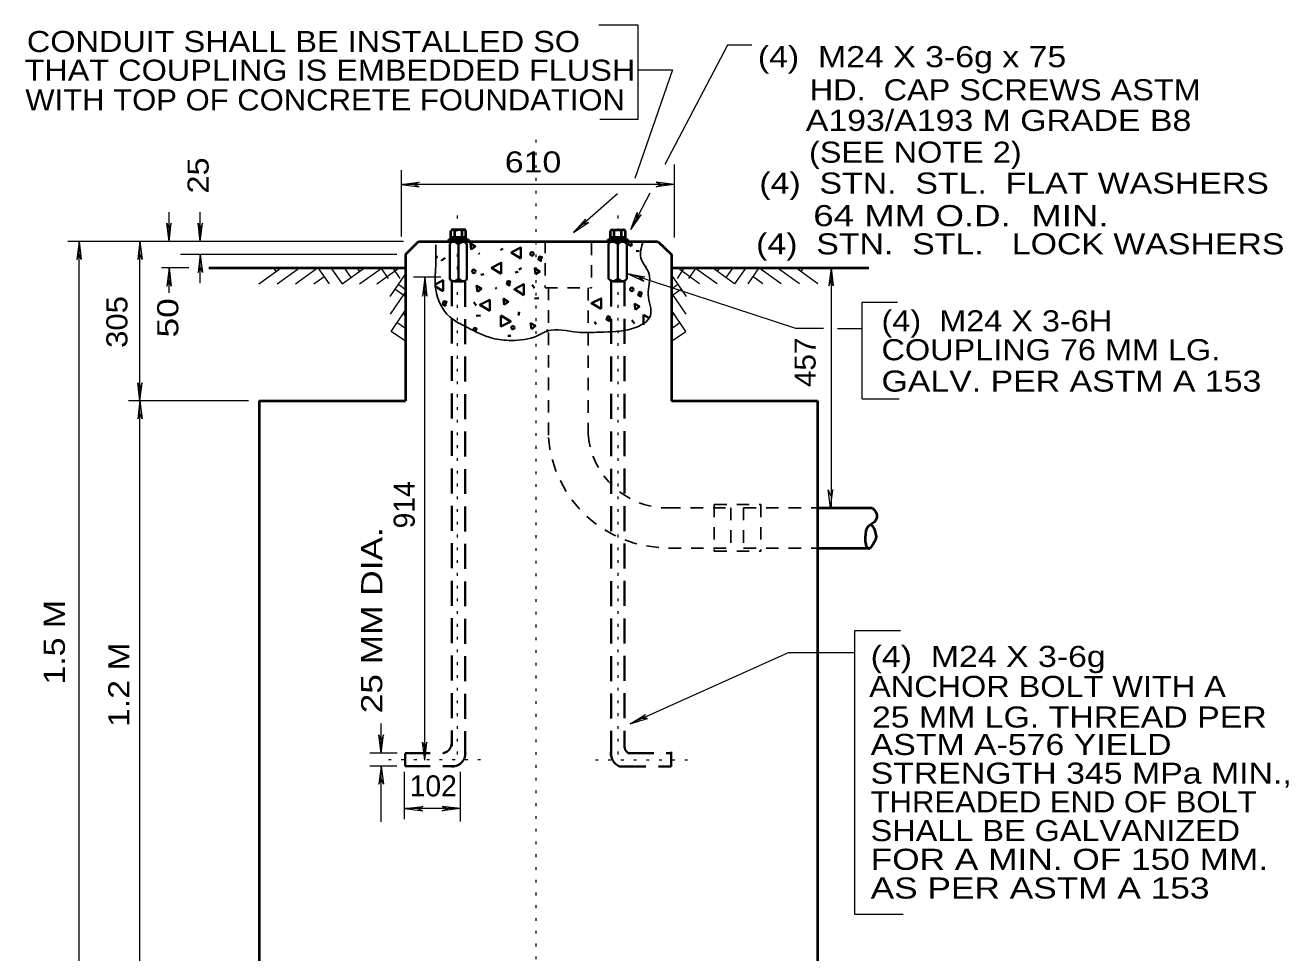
# Model space of a CAD drawing. Extents: x 312583 to 312854, y 144419 to 144597.
# Drawn here: x 312759.06 to 312804.6, y 144492.78 to 144526.21 of the extents above; entities that cross this region are included whole.
import ezdxf

# ---------------------------------------------------------------- set-up
doc = ezdxf.new("R2010")
doc.units = 0
doc.header["$LTSCALE"] = 0.3
for name, pattern in [('DOTTED', [1.5, 0.3, -1.2]), ('MEDIUM_DASHED', [4.5, 3, -1.5]), ('SHORT_DASHED', [2.7, 1.5, -1.2])]:
    doc.linetypes.add(name, pattern=pattern)
doc.layers.add('1', color=7, linetype='Continuous', lineweight=25)
doc.layers.add('2', color=7, linetype='Continuous', lineweight=13)

msp = doc.modelspace()

# ---------------------------------------------------------------- linework, layer by layer
at = {"layer": '1', "linetype": 'DOTTED', "lineweight": 13}
for p, q in [((312774.6248, 144519.352), (312774.6248, 144499.8557)), ((312780.4208, 144519.352), (312780.4208, 144499.8557)), ((312772.1485, 144499.7407), (312775.4988, 144499.7407)), ((312779.6081, 144499.733), (312782.9431, 144499.733))]:
    msp.add_line(p, q, dxfattribs=at)
at = {"layer": '1', "lineweight": 40}
for p, q in [((312774.4025, 144518.4857), (312774.4025, 144518.8)), ((312774.4025, 144518.5777), (312774.9391, 144518.5777)), ((312774.4715, 144518.846), (312774.8778, 144518.846)), ((312774.5405, 144518.5777), (312774.5405, 144518.8)), ((312774.8088, 144518.5777), (312774.8088, 144518.8)), ((312774.9391, 144518.4857), (312774.9391, 144518.8)), ((312780.1525, 144518.4857), (312780.1525, 144518.8)), ((312780.1525, 144518.57), (312780.6891, 144518.57)), ((312780.2138, 144518.8384), (312780.6201, 144518.8384)), ((312780.2828, 144518.57), (312780.2828, 144518.8)), ((312780.5511, 144518.57), (312780.5511, 144518.8)), ((312780.6891, 144518.4857), (312780.6891, 144518.8)), ((312772.7618, 144517.949), (312773.2371, 144518.4244)), ((312773.2371, 144518.4244), (312781.8621, 144518.4244)), ((312774.3105, 144518.4857), (312775.0311, 144518.4857)), ((312774.3105, 144518.4857), (312774.3105, 144518.4244)), ((312775.0311, 144518.4857), (312775.0311, 144518.4244)), ((312780.0605, 144518.4857), (312780.7811, 144518.4857)), ((312780.0605, 144518.4857), (312780.0605, 144518.4244)), ((312780.7735, 144518.4857), (312780.7735, 144518.4244)), ((312781.8621, 144518.4244), (312782.3451, 144517.949)), ((312772.7618, 144517.949), (312772.7618, 144512.6744)), ((312782.3451, 144517.949), (312782.3451, 144512.6744)), ((312765.6701, 144517.466), (312772.7618, 144517.466)), ((312782.3451, 144517.466), (312789.4598, 144517.466)), ((312774.5251, 144516.9907), (312774.8318, 144516.9907)), ((312780.2598, 144516.9907), (312780.5818, 144516.9907)), ((312767.4871, 144512.6744), (312767.4871, 144489.6744)), ((312767.4871, 144512.6744), (312772.7618, 144512.6744)), ((312782.3451, 144512.6744), (312787.6121, 144512.6744)), ((312787.6121, 144512.6744), (312787.6121, 144489.6744)), ((312787.6351, 144508.818), (312789.5825, 144508.818)), ((312787.6351, 144507.369), (312789.4828, 144507.369))]:
    msp.add_line(p, q, dxfattribs=at)
at = {"layer": '1', "lineweight": 35}
for p, q in [((312774.3565, 144518.34), (312774.3565, 144517.0444)), ((312774.6708, 144518.3247), (312774.6708, 144517.0597)), ((312774.9775, 144518.34), (312774.9775, 144517.0444)), ((312776.1811, 144518.11), (312776.2731, 144518.1637)), ((312780.0835, 144518.34), (312780.0835, 144517.0674)), ((312780.4208, 144518.3477), (312780.4208, 144517.052)), ((312780.6048, 144518.432), (312780.9115, 144518.248)), ((312780.7351, 144518.34), (312780.7351, 144517.0597)), ((312780.9115, 144518.248), (312780.9115, 144518.4397)), ((312781.0725, 144518.0717), (312781.1875, 144518.087)), ((312774.1878, 144517.8264), (312774.0498, 144517.7267)), ((312775.4068, 144517.995), (312775.4298, 144517.9567)), ((312775.4835, 144517.2207), (312775.5908, 144517.2437)), ((312776.7178, 144517.305), (312776.8251, 144517.328)), ((312776.8481, 144517.4047), (312776.9401, 144517.4584)), ((312773.8428, 144516.799), (312774.1188, 144516.6304)), ((312776.0048, 144516.7607), (312776.0431, 144516.707)), ((312777.3235, 144516.8604), (312777.4155, 144516.7377)), ((312777.4078, 144516.3697), (312777.5688, 144516.3774)), ((312775.2228, 144516.2317), (312775.3148, 144516.109)), ((312776.8405, 144515.7487), (312776.8558, 144515.8867)), ((312775.3148, 144515.741), (312775.4681, 144515.7487)), ((312779.5698, 144515.5264), (312779.6388, 144515.4344)), ((312780.9191, 144515.58), (312781.0111, 144515.465)), ((312781.3408, 144515.7794), (312781.3408, 144515.419)), ((312781.5325, 144515.6644), (312781.3408, 144515.7794)), ((312775.2918, 144515.1737), (312775.2918, 144515.2197)), ((312776.4571, 144515.0127), (312776.5645, 144515.0127)), ((312777.8908, 144515.2504), (312777.8525, 144515.166))]:
    msp.add_line(p, q, dxfattribs=at)
at = {"layer": '1', "linetype": 'SHORT_DASHED'}
for p, q in [((312777.7911, 144518.4474), (312777.7911, 144516.7454)), ((312779.4701, 144518.3784), (312779.4701, 144516.7454)), ((312777.7911, 144516.7454), (312779.4701, 144516.7454)), ((312777.9215, 144516.753), (312777.9215, 144511.371)), ((312779.3475, 144516.7454), (312779.3475, 144511.463)), ((312782.2301, 144508.818), (312784.4918, 144508.818)), ((312783.8938, 144508.933), (312785.5651, 144508.933)), ((312783.8938, 144508.933), (312783.8938, 144507.254)), ((312784.4918, 144508.818), (312784.4918, 144507.369)), ((312784.9518, 144508.818), (312784.9518, 144507.369)), ((312784.9518, 144508.818), (312787.5968, 144508.818)), ((312785.5651, 144508.933), (312785.5651, 144507.254)), ((312782.2455, 144507.369), (312784.4918, 144507.369)), ((312783.8938, 144507.254), (312785.5651, 144507.254)), ((312784.9518, 144507.369), (312787.5891, 144507.369))]:
    msp.add_line(p, q, dxfattribs=at)
at = {"layer": '1', "linetype": 'MEDIUM_DASHED', "lineweight": 35}
for p, q in [((312774.4331, 144516.9907), (312774.4331, 144500.2314)), ((312774.9161, 144516.9677), (312774.9161, 144499.802)), ((312780.1755, 144516.9754), (312780.1755, 144499.871)), ((312780.6585, 144516.983), (312780.6585, 144500.17)), ((312772.7541, 144499.9784), (312774.1188, 144499.9784)), ((312772.7541, 144499.963), (312772.7541, 144499.503)), ((312780.8118, 144499.9784), (312782.3375, 144499.9784)), ((312782.3375, 144500.0167), (312782.3375, 144499.4954)), ((312772.7541, 144499.503), (312774.5251, 144499.503)), ((312780.5281, 144499.4954), (312782.3375, 144499.4954))]:
    msp.add_line(p, q, dxfattribs=at)
at = {"layer": '1', "lineweight": 35}
for points in [[(312775.1308, 144518.133), (312775.2765, 144518.2404), (312775.1001, 144518.3477)], [(312776.9248, 144517.811), (312776.9248, 144518.202), (312776.5721, 144518.0257)], [(312776.2118, 144517.259), (312776.2118, 144517.65), (312775.8668, 144517.4737)], [(312777.6455, 144517.788), (312777.6838, 144517.8494), (312777.5918, 144517.8724), (312777.5535, 144517.765), (312777.6455, 144517.7114)], [(312777.4538, 144517.236), (312777.5995, 144517.3434), (312777.4231, 144517.4507)], [(312776.5108, 144516.914), (312776.5415, 144516.9754), (312776.4571, 144516.9984), (312776.4111, 144516.8834), (312776.5108, 144516.8297)], [(312777.0321, 144516.4847), (312777.0321, 144516.8757), (312776.6871, 144516.6994)], [(312774.2031, 144516.1857), (312774.2415, 144516.247), (312774.1495, 144516.27), (312774.1035, 144516.155), (312774.2031, 144516.1014)], [(312775.7978, 144515.925), (312775.7978, 144516.316), (312775.4451, 144516.1397)], [(312776.3191, 144516.1397), (312776.4648, 144516.247), (312776.2961, 144516.3544)], [(312779.8151, 144515.9864), (312779.8151, 144516.3697), (312779.4625, 144516.1934)], [(312781.2411, 144516.5077), (312781.2795, 144516.569), (312781.1951, 144516.5997), (312781.1491, 144516.4847), (312781.2411, 144516.431)], [(312781.0495, 144515.9557), (312781.1951, 144516.0707), (312781.0188, 144516.1704)], [(312776.2041, 144515.7487), (312776.2041, 144515.3577), (312776.5568, 144515.534)], [(312777.3005, 144515.258), (312777.4461, 144515.373), (312777.2698, 144515.4727)], [(312780.1065, 144515.6337), (312780.1371, 144515.695), (312780.0528, 144515.7257), (312780.0068, 144515.6107), (312780.1065, 144515.557)]]:
    msp.add_lwpolyline(points, close=True, dxfattribs=at)
for points in [[(312773.8505, 144517.8187), (312773.9041, 144517.8647), (312773.8428, 144517.8954)], [(312781.4328, 144517.5197), (312781.4328, 144517.512), (312781.4481, 144517.5044)], [(312774.1188, 144516.6304), (312774.1188, 144517.0214), (312773.8505, 144516.8834)], [(312775.4988, 144516.7147), (312775.4988, 144516.7147), (312775.3225, 144516.822), (312775.3531, 144516.6074)], [(312775.3531, 144516.6074), (312775.4988, 144516.7147), (312775.4988, 144516.7147)], [(312775.2918, 144515.2197), (312775.3225, 144515.281), (312775.2381, 144515.304), (312775.1998, 144515.212)]]:
    msp.add_lwpolyline(points, dxfattribs=at)
for centre, radius in [((312777.3221, 144517.9723), 0.0649), ((312775.2252, 144517.3437), 0.0649), ((312780.9198, 144516.6946), 0.0649), ((312776.634, 144515.3122), 0.0588)]:
    msp.add_circle(centre, radius, dxfattribs=at)
at = {"layer": '1', "lineweight": 40}
for centre, radius, start, end in [((312774.4707, 144518.7725), 0.0735, 23.18435, 156.81565), ((312774.6731, 144518.62), 0.2261, 53.40512, 126.59488), ((312774.875, 144518.7731), 0.073, 22.90211, 157.09789), ((312780.2164, 144518.7687), 0.0735, 23.18435, 156.81565), ((312780.4188, 144518.6161), 0.2261, 53.40512, 126.59488), ((312780.6207, 144518.7692), 0.073, 22.90211, 157.09789)]:
    msp.add_arc(centre, radius, start, end, dxfattribs=at)
at = {"layer": '1', "linetype": 'SHORT_DASHED'}
for radius in [4.3125, 2.875]:
    msp.add_arc((312782.2177, 144511.6873), radius, 184.41706, 270, dxfattribs=at)
at = {"layer": '1', "linetype": 'MEDIUM_DASHED', "lineweight": 35}
for centre, radius, start, end in [((312774.0509, 144500.3456), 0.3772, 279.93307, 6.75077), ((312774.4507, 144499.9667), 0.4689, 260.30828, 14.04371)]:
    msp.add_arc(centre, radius, start, end, dxfattribs=at)
at = {"layer": '1', "lineweight": 35}
for points in [[(312774.3565, 144518.34), (312774.5098, 144518.4244), (312774.6708, 144518.3324), (312774.8318, 144518.4244), (312774.9775, 144518.3247)], [(312780.0835, 144518.34), (312780.2368, 144518.4244), (312780.4208, 144518.3477), (312780.5741, 144518.4244), (312780.7351, 144518.34)], [(312774.3565, 144517.0444), (312774.5251, 144516.9907), (312774.6785, 144517.0597), (312774.8395, 144516.9907), (312774.9775, 144517.052)], [(312780.0835, 144517.0674), (312780.2598, 144516.9907), (312780.4208, 144517.0597), (312780.5741, 144516.9907), (312780.7275, 144517.0597)]]:
    msp.add_spline(points, degree=3, dxfattribs=at)
at = {"layer": '1', "lineweight": 40}
msp.add_spline([(312789.5825, 144508.818), (312789.7281, 144508.6417), (312789.7511, 144508.4577), (312789.7051, 144508.358), (312789.5748, 144508.243), (312789.4368, 144508.1434), (312789.3678, 144508.0207), (312789.3448, 144507.8904), (312789.3295, 144507.6834), (312789.3525, 144507.507), (312789.3985, 144507.392), (312789.4291, 144507.3614), (312789.5901, 144507.461), (312789.6591, 144507.576), (312789.7281, 144507.7217), (312789.7051, 144507.944), (312789.6438, 144508.0974), (312789.5288, 144508.2124)], degree=3, dxfattribs=at)
at = {"layer": '2'}
for p, q in [((312782.3911, 144524.6114), (312781.0265, 144520.686)), ((312781.1535, 144524.6114), (312782.3911, 144524.6114)), ((312781.1535, 144522.8186), (312779.7732, 144522.8186)), ((312772.6008, 144520.9927), (312772.6008, 144518.6007)), ((312782.4448, 144521.1997), (312782.4448, 144518.5624)), ((312772.6008, 144520.4714), (312773.2525, 144520.5557)), ((312782.4448, 144520.4714), (312772.6008, 144520.4714)), ((312772.6008, 144520.4714), (312773.2525, 144520.3947)), ((312773.2525, 144520.5557), (312773.0455, 144520.4714)), ((312773.2525, 144520.3947), (312773.0455, 144520.4714)), ((312781.7931, 144520.5557), (312782.0001, 144520.4714)), ((312782.4448, 144520.4714), (312781.7931, 144520.5557)), ((312781.7931, 144520.3947), (312782.0001, 144520.4714)), ((312782.4448, 144520.4714), (312781.7931, 144520.3947)), ((312780.4055, 144520.134), (312778.8185, 144518.7387)), ((312781.5708, 144520.157), (312780.8808, 144518.846)), ((312764.2441, 144518.4244), (312764.2441, 144519.4747)), ((312765.3635, 144518.4244), (312765.3635, 144519.4747)), ((312780.8808, 144518.846), (312781.1108, 144519.4594)), ((312781.1108, 144519.4594), (312781.0878, 144519.237)), ((312764.1598, 144519.076), (312764.2441, 144518.869)), ((312764.2441, 144518.4244), (312764.1598, 144519.076)), ((312764.3208, 144519.076), (312764.2441, 144518.869)), ((312764.2441, 144518.4244), (312764.3208, 144519.076)), ((312765.2868, 144519.076), (312765.3635, 144518.869)), ((312765.3635, 144518.4244), (312765.2868, 144519.076)), ((312765.4478, 144519.076), (312765.3635, 144518.869)), ((312765.3635, 144518.4244), (312765.4478, 144519.076)), ((312778.8185, 144518.7387), (312779.2478, 144519.2294)), ((312778.8185, 144518.7387), (312779.3551, 144519.1067)), ((312779.2478, 144519.2294), (312779.1481, 144519.03)), ((312779.3551, 144519.1067), (312779.1481, 144519.03)), ((312780.8808, 144518.846), (312781.2565, 144519.3827)), ((312781.2565, 144519.3827), (312781.0878, 144519.237)), ((312772.6851, 144518.4244), (312760.5871, 144518.4244)), ((312761.0011, 144518.4244), (312760.9168, 144517.7727)), ((312761.0011, 144518.4244), (312761.0778, 144517.7727)), ((312761.0011, 144489.6667), (312761.0011, 144518.4244)), ((312763.1861, 144518.4244), (312763.1095, 144517.7727)), ((312763.1861, 144518.4244), (312763.2705, 144517.7727)), ((312760.9168, 144517.7727), (312761.0011, 144517.9797)), ((312761.0778, 144517.7727), (312761.0011, 144517.9797)), ((312763.1095, 144517.7727), (312763.1861, 144517.9797)), ((312763.2705, 144517.7727), (312763.1861, 144517.9797)), ((312772.4475, 144517.949), (312764.6505, 144517.949)), ((312765.3635, 144517.949), (312765.2868, 144517.2974)), ((312765.3635, 144516.914), (312765.3635, 144517.949)), ((312765.3635, 144517.949), (312765.4478, 144517.2974)), ((312764.9571, 144517.466), (312763.9681, 144517.466)), ((312764.2441, 144517.466), (312764.1598, 144516.8144)), ((312764.2441, 144516.569), (312764.2441, 144517.466)), ((312764.2441, 144517.466), (312764.3208, 144516.8144)), ((312765.2868, 144517.2974), (312765.3635, 144517.5044)), ((312765.4478, 144517.2974), (312765.3635, 144517.5044)), ((312767.4795, 144516.8987), (312768.2768, 144517.466)), ((312768.0008, 144517.466), (312768.0928, 144517.3357)), ((312768.1388, 144516.8987), (312768.9361, 144517.466)), ((312768.7981, 144516.8987), (312769.5955, 144517.466)), ((312769.6031, 144517.466), (312770.0095, 144516.8987)), ((312770.0708, 144517.466), (312770.4771, 144516.8987)), ((312770.4771, 144516.8987), (312771.2821, 144517.466)), ((312770.5461, 144517.466), (312770.7915, 144517.121)), ((312771.0138, 144517.466), (312771.1058, 144517.3434)), ((312771.1058, 144516.8987), (312771.8801, 144517.4507)), ((312771.7345, 144516.8987), (312772.5395, 144517.466)), ((312771.8878, 144517.4507), (312772.1408, 144517.0827)), ((312772.2098, 144516.431), (312772.7618, 144517.2437)), ((312772.3018, 144517.4584), (312772.5548, 144517.0904)), ((312780.7505, 144517.2667), (312781.3485, 144516.9907)), ((312780.7505, 144517.2667), (312781.3945, 144517.144)), ((312782.8895, 144516.431), (312782.3375, 144517.2437)), ((312782.7975, 144517.4584), (312782.5521, 144517.0904)), ((312783.3648, 144516.8987), (312782.5675, 144517.466)), ((312783.2115, 144517.4507), (312782.9661, 144517.0827)), ((312784.0011, 144516.8987), (312783.2191, 144517.4507)), ((312784.6221, 144516.8987), (312783.8248, 144517.466)), ((312784.0855, 144517.466), (312784.0011, 144517.3434)), ((312784.5608, 144517.466), (312784.3078, 144517.121)), ((312785.0285, 144517.466), (312784.6221, 144516.8987)), ((312785.4961, 144517.466), (312785.0975, 144516.8987)), ((312786.3011, 144516.8987), (312785.5038, 144517.466)), ((312786.9605, 144516.8987), (312786.1631, 144517.466)), ((312787.6198, 144516.8987), (312786.8301, 144517.466)), ((312787.0985, 144517.466), (312787.0141, 144517.3357)), ((312788.1028, 144517.4737), (312788.0185, 144516.822)), ((312788.1028, 144517.4737), (312788.1795, 144516.822)), ((312788.1028, 144517.3357), (312788.1028, 144508.8487)), ((312764.1598, 144516.8144), (312764.2441, 144517.0214)), ((312764.3208, 144516.8144), (312764.2441, 144517.0214)), ((312769.4575, 144516.8987), (312769.8255, 144517.1594)), ((312772.5241, 144516.868), (312772.7541, 144516.6994)), ((312774.0345, 144517.1287), (312773.0455, 144517.1287)), ((312773.4595, 144517.1057), (312773.3751, 144516.454)), ((312773.4595, 144499.7254), (312773.4595, 144517.1057)), ((312773.4595, 144517.1057), (312773.5361, 144516.454)), ((312781.3945, 144517.144), (312781.1721, 144517.1287)), ((312781.3485, 144516.9907), (312781.1721, 144517.1287)), ((312782.5828, 144516.868), (312782.3451, 144516.6994)), ((312785.6418, 144516.8987), (312785.2815, 144517.1594)), ((312788.0185, 144516.822), (312788.1028, 144517.029)), ((312788.1795, 144516.822), (312788.1028, 144517.029)), ((312772.2251, 144515.8024), (312772.7618, 144516.592)), ((312772.4168, 144516.6917), (312772.7541, 144516.454)), ((312773.3751, 144516.454), (312773.4595, 144516.661)), ((312773.5361, 144516.454), (312773.4595, 144516.661)), ((312782.8818, 144515.8024), (312782.3375, 144516.592)), ((312782.6901, 144516.6917), (312782.3451, 144516.454)), ((312772.2405, 144515.1737), (312772.7618, 144515.9404)), ((312772.7618, 144515.7487), (312772.6698, 144515.81)), ((312782.8665, 144515.1737), (312782.3451, 144515.9404)), ((312782.3451, 144515.7487), (312782.4371, 144515.81)), ((312772.7618, 144515.281), (312772.4551, 144515.4957)), ((312782.3451, 144515.281), (312782.6518, 144515.4957)), ((312772.7618, 144514.821), (312772.2405, 144515.1737)), ((312782.3451, 144514.821), (312782.8665, 144515.1737)), ((312788.3328, 144515.281), (312789.2195, 144515.281)), ((312763.1095, 144513.326), (312763.1861, 144513.119)), ((312763.1861, 144512.6744), (312763.1095, 144513.326)), ((312763.2705, 144513.326), (312763.1861, 144513.119)), ((312763.1861, 144512.6744), (312763.2705, 144513.326)), ((312767.1038, 144512.6744), (312762.7798, 144512.6744)), ((312763.1861, 144512.6744), (312763.1095, 144512.0227)), ((312763.1861, 144512.6744), (312763.2705, 144512.0227)), ((312789.2195, 144512.7443), (312790.5612, 144512.7443)), ((312763.1095, 144512.0227), (312763.1861, 144512.2297)), ((312763.2705, 144512.0227), (312763.1861, 144512.2297)), ((312788.0031, 144509.4697), (312788.0875, 144509.2627)), ((312788.0875, 144508.818), (312788.0031, 144509.4697)), ((312788.1641, 144509.4697), (312788.0875, 144509.2627)), ((312788.0875, 144508.818), (312788.1641, 144509.4697)), ((312767.4948, 144506.9014), (312767.4948, 144507.2847)), ((312767.4948, 144506.9014), (312767.4948, 144506.518)), ((312788.9615, 144504.3944), (312790.6021, 144504.3944)), ((312788.9615, 144494.1747), (312788.9615, 144504.3944)), ((312767.4948, 144501.9104), (312767.4948, 144493.316)), ((312780.8578, 144501.0364), (312781.4175, 144501.3737)), ((312781.4175, 144501.3737), (312781.2641, 144501.2204)), ((312771.8801, 144499.9784), (312771.8801, 144501.044)), ((312780.8578, 144501.0364), (312781.4865, 144501.228)), ((312781.4865, 144501.228), (312781.2641, 144501.2204)), ((312771.8035, 144500.63), (312771.8801, 144500.423)), ((312771.8801, 144499.9784), (312771.8035, 144500.63)), ((312771.9645, 144500.63), (312771.8801, 144500.423)), ((312771.8801, 144499.9784), (312771.9645, 144500.63)), ((312773.3751, 144500.377), (312773.4595, 144500.17)), ((312773.4595, 144499.7254), (312773.3751, 144500.377)), ((312773.5361, 144500.377), (312773.4595, 144500.17)), ((312773.4595, 144499.7254), (312773.5361, 144500.377)), ((312772.4628, 144499.9784), (312771.4738, 144499.9784)), ((312772.4551, 144499.503), (312771.4738, 144499.503)), ((312771.8801, 144499.503), (312771.8035, 144498.8514)), ((312771.8801, 144499.503), (312771.9645, 144498.8514)), ((312771.8801, 144497.502), (312771.8801, 144499.48)), ((312771.8035, 144498.8514), (312771.8801, 144499.0584)), ((312771.9645, 144498.8514), (312771.8801, 144499.0584)), ((312772.7311, 144497.594), (312772.7311, 144499.296)), ((312774.7398, 144497.5097), (312774.7398, 144499.296)), ((312772.7311, 144497.9774), (312773.3828, 144498.054)), ((312773.3828, 144498.054), (312773.1758, 144497.9774)), ((312774.0881, 144498.054), (312774.2951, 144497.9774)), ((312774.7398, 144497.9774), (312774.0881, 144498.054)), ((312774.7398, 144497.9774), (312772.7311, 144497.9774)), ((312772.7311, 144497.9774), (312773.3828, 144497.893)), ((312773.3828, 144497.893), (312773.1758, 144497.9774)), ((312774.0881, 144497.893), (312774.2951, 144497.9774)), ((312774.7398, 144497.9774), (312774.0881, 144497.893)), ((312788.9615, 144494.1747), (312790.7018, 144494.1747))]:
    msp.add_line(p, q, dxfattribs=at)
at = {"layer": '2', "linetype": 'DOTTED'}
for p, q in [((312777.4691, 144485.1894), (312777.4691, 144522.3114)), ((312767.4948, 144507.4764), (312767.4948, 144511.3097)), ((312767.4948, 144506.3264), (312767.4948, 144502.493))]:
    msp.add_line(p, q, dxfattribs=at)
at = {"layer": '2'}
for points in [[(312781.1535, 144522.8186), (312781.1535, 144526.2137), (312779.7272, 144526.2137)], [(312785.2508, 144525.493), (312784.3691, 144525.493), (312782.1151, 144521.1997)], [(312763.1861, 144489.6744), (312763.1861, 144512.6744), (312763.1861, 144518.4244)], [(312787.8268, 144515.281), (312786.8378, 144515.281), (312780.8578, 144517.236)], [(312789.2195, 144512.7443), (312789.2195, 144516.2326), (312790.4922, 144516.2326)], [(312788.9615, 144503.5894), (312786.5618, 144503.5894), (312780.8578, 144501.0364)]]:
    msp.add_lwpolyline(points, dxfattribs=at)
at = {"layer": '2', "linetype": 'MEDIUM_DASHED', "lineweight": 35}
for centre, radius, start, end in [((312780.6754, 144499.9664), 0.5094, 174.06126, 254.81867), ((312780.9403, 144500.2196), 0.2809, 181.69896, 244.53737)]:
    msp.add_arc(centre, radius, start, end, dxfattribs=at)
at = {"layer": '2', "lineweight": 25}
msp.add_spline([(312773.8505, 144518.3017), (312773.8505, 144517.535), (312773.8505, 144516.684), (312774.3565, 144515.7027), (312774.9928, 144515.3194), (312775.8898, 144514.936), (312776.5721, 144514.8517), (312777.5075, 144515.0204), (312777.8908, 144515.1967), (312778.9565, 144515.1507), (312779.7615, 144515.1507), (312780.9498, 144515.281), (312781.5938, 144515.7487), (312781.5095, 144516.5154), (312781.5478, 144517.236), (312781.2488, 144517.834), (312781.3331, 144518.4244)], degree=3, dxfattribs=at)

# ---------------------------------------------------------------- texts
at = {"layer": '1', "width": 1.05}
msp.add_text('457', height=0.76, rotation=90, dxfattribs=at).set_placement((312787.5447, 144513.1717))
at = {"layer": '2'}
for s, width, p in [('CONDUIT SHALL BE INSTALLED SO', 1.15, (312759.1151, 144525.2488)), ('(4)  M24 X 3-6g x 75', 1.2, (312785.4627, 144524.7024)), ('THAT COUPLING IS EMBEDDED FLUSH', 1.15, (312759.0312, 144524.2139)), ('HD.  CAP SCREWS ASTM', 1.15, (312787.3334, 144523.5074)), ('WITH TOP OF CONCRETE FOUNDATION', 1.1, (312759.0598, 144523.1429)), ('A193/A193 M GRADE B8', 1.2, (312787.1914, 144522.4058)), ('(SEE NOTE 2)', 1.15, (312787.3077, 144521.2586)), ('610 ', 1.2, (312776.3427, 144520.9067)), ('(4)  STN.  STL.  FLAT WASHERS', 1.2, (312785.5174, 144520.1446)), ('64 MM O.D.  MIN.', 1.3, (312787.4605, 144518.9711)), ('(4)  STN.  STL.   LOCK WASHERS', 1.2, (312785.4016, 144517.9544)), ('(4)  M24 X 3-6H', 1.15, (312789.9219, 144515.1781)), ('COUPLING 76 MM LG.', 1.15, (312789.9203, 144514.1378)), ('GALV. PER ASTM A 153', 1.2, (312789.9207, 144513.008)), ('(4)  M24 X 3-6g ', 1.2, (312789.5288, 144503.0824)), ('ANCHOR BOLT WITH A', 1.15, (312789.4751, 144502.0014)), ('25 MM LG. THREAD PER', 1.2, (312789.5748, 144500.8974)), ('ASTM A-576 YIELD', 1.2, (312789.5288, 144499.9084)), ('STRENGTH 345 MPa MIN.,', 1.2, (312789.5288, 144498.8734)), ('THREADED END OF BOLT', 1.1, (312789.5288, 144497.8384)), ('SHALL BE GALVANIZED ', 1.15, (312789.5288, 144496.8034)), ('FOR A MIN. OF 150 MM.', 1.25, (312789.5288, 144495.7684)), ('AS PER ASTM A 153', 1.25, (312789.5288, 144494.7334))]:
    msp.add_text(s, height=0.76, dxfattribs=dict(at, width=width)).set_placement(p)
for s, width, p in [('25 ', 1.15, (312765.6662, 144520.1487)), ('305', 1.1, (312762.739, 144514.5848)), ('50 ', 1.25, (312764.5731, 144514.9594)), ('25 MM DIA.', 1.25, (312771.9241, 144501.4115)), ('1.5 M', 1.2, (312760.485, 144502.4485)), ('1.2 M', 1.2, (312762.808, 144500.9165))]:
    msp.add_text(s, height=0.76, rotation=90, dxfattribs=dict(at, width=width)).set_placement(p)
msp.add_text('914', height=0.76, rotation=90, dxfattribs=at).set_placement((312773.0947, 144508.0776))
msp.add_text('102', height=0.76, dxfattribs=at).set_placement((312772.9149, 144498.4152))

doc.saveas('drawing.dxf')
